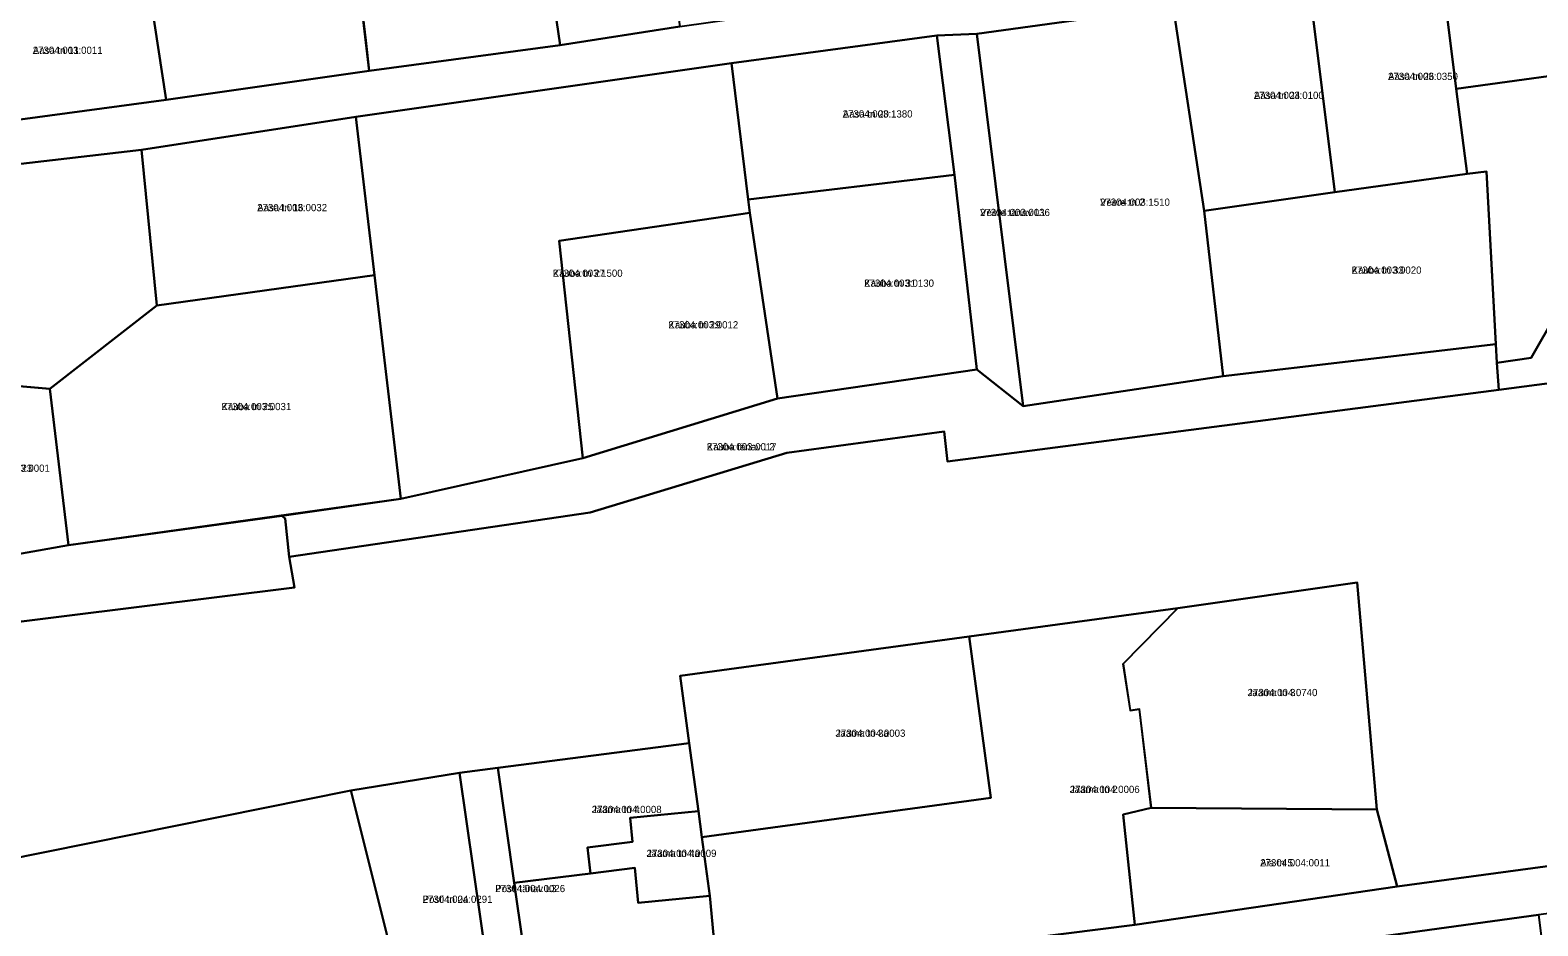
# Model space of a CAD drawing. Extents: x 603789 to 628102, y 6569852 to 6597259.
# Drawn here: x 622067.3 to 622380.3, y 6579689.4 to 6579875.4 of the extents above; entities that cross this region are included whole.
import ezdxf

# ---------------------------------------------------------------- set-up
doc = ezdxf.new("R2010")
doc.units = 0
for name, color, linetype in [('L_AADRESS', 7, 'Continuous'), ('PIIR', 7, 'Continuous'), ('TUNNUS', 7, 'Continuous')]:
    doc.layers.add(name, color=color, linetype=linetype)

msp = doc.modelspace()

# ---------------------------------------------------------------- linework, layer by layer
at = {"layer": 'PIIR'}
for points in [[(622170.72, 6579917.77), (622170.43, 6579919.31), (622194.97, 6579923.91), (622202.17, 6579876.21), (622177.32, 6579872.32)], [(622134.28, 6579895.91), (622132.4, 6579913.28), (622170.43, 6579919.31), (622170.72, 6579917.77), (622177.32, 6579872.32), (622137.73, 6579866.98)], [(622095.55, 6579860.95), (622091.61, 6579886.88), (622091.14, 6579889.62), (622113.84, 6579893.19), (622134.28, 6579895.91), (622136.98, 6579873.27), (622137.73, 6579866.98)], [(622360.27, 6579888.32), (622399.48, 6579895.23), (622401.63, 6579868.51), (622396.67, 6579867.81), (622363.4, 6579863.22)], [(622332.84, 6579884.63), (622360.27, 6579888.32), (622363.4, 6579863.22), (622365.62, 6579845.6), (622338.16, 6579841.8)], [(622091.61, 6579886.88), (622095.55, 6579860.95), (622044.62, 6579854.13), (622040.03, 6579879.14), (622067.85, 6579883.26)], [(622311.03, 6579837.93), (622304.61, 6579880.29), (622332.84, 6579884.63), (622338.16, 6579841.8)], [(622372.24, 6579800.71), (622371.83, 6579806.31), (622378.93, 6579807.36), (622399.14, 6579842.64), (622396.67, 6579867.81), (622401.63, 6579868.51), (622449.04, 6579874.75), (622522.3, 6579884.79), (622526.56, 6579866.38), (622539.24, 6579867.89), (622546.93, 6579836.13), (622548.52, 6579823.88)], [(622263.84, 6579874.66), (622304.61, 6579880.29), (622311.03, 6579837.93), (622315.01, 6579803.58), (622273.45, 6579797.29)], [(622212.9, 6579868.55), (622255.58, 6579874.31), (622259.25, 6579845.36), (622216.37, 6579840.25)], [(622255.58, 6579874.31), (622263.84, 6579874.66), (622273.45, 6579797.29), (622263.88, 6579804.9), (622259.25, 6579845.36)], [(622138.81, 6579824.51), (622134.92, 6579857.44), (622212.9, 6579868.55), (622216.37, 6579840.25), (622216.72, 6579837.46), (622177.17, 6579831.67), (622182.03, 6579786.5), (622144.3, 6579778.1)], [(622365.62, 6579845.6), (622363.4, 6579863.22), (622396.67, 6579867.81), (622399.14, 6579842.64), (622378.93, 6579807.36), (622371.83, 6579806.31), (622371.57, 6579810.23), (622369.66, 6579846.08)], [(622090.44, 6579850.56), (622134.92, 6579857.44), (622138.81, 6579824.51), (622093.61, 6579818.2)], [(621965.04, 6579811.57), (621962.83, 6579826.78), (621961.56, 6579835.58), (622090.44, 6579850.56), (622093.61, 6579818.2), (622071.41, 6579800.89), (622029.32, 6579804.59), (622028.08, 6579814.64), (622012.35, 6579813.75)], [(622222.48, 6579798.88), (622216.72, 6579837.46), (622216.37, 6579840.25), (622259.25, 6579845.36), (622263.88, 6579804.9)], [(622369.66, 6579846.08), (622371.57, 6579810.23), (622315.01, 6579803.58), (622311.03, 6579837.93), (622338.16, 6579841.8), (622365.62, 6579845.6)], [(622177.17, 6579831.67), (622216.72, 6579837.46), (622222.48, 6579798.88), (622182.03, 6579786.5)], [(622075.29, 6579768.47), (622071.41, 6579800.89), (622093.61, 6579818.2), (622138.81, 6579824.51), (622144.3, 6579778.1)], [(622119.58, 6579774.56), (622144.3, 6579778.1), (622182.03, 6579786.5), (622222.48, 6579798.88), (622263.88, 6579804.9), (622273.45, 6579797.29), (622315.01, 6579803.58), (622371.57, 6579810.23), (622371.83, 6579806.31), (622372.24, 6579800.71), (622257.76, 6579785.82), (622257.04, 6579792.02), (622224.39, 6579787.62), (622183.59, 6579775.25), (622121.09, 6579766.04), (622120.23, 6579773.96)], [(622071.41, 6579800.89), (622075.29, 6579768.47), (622044.4, 6579762.97), (622041.92, 6579764.98), (622038.53, 6579803.78)], [(622300.05, 6579713.85), (622297.61, 6579734.35), (622295.76, 6579734.07), (622294.24, 6579743.81), (622305.59, 6579755.32), (622342.78, 6579760.66), (622346.87, 6579713.5)], [(622305.59, 6579755.32), (622294.2, 6579743.81), (622295.71, 6579734.08), (622297.56, 6579734.35), (622300.05, 6579713.85), (622294.2, 6579712.49), (622296.66, 6579689.57), (622210.05, 6579678.6), (622208.44, 6579695.58), (622206.78, 6579707.81), (622266.78, 6579715.93), (622262.25, 6579749.45)], [(622206.78, 6579707.81), (622206.06, 6579713.17), (622204.15, 6579727.31), (622202.25, 6579741.32), (622262.25, 6579749.45), (622266.78, 6579715.93)], [(622164.38, 6579722.17), (622204.15, 6579727.31), (622206.06, 6579713.17), (622191.88, 6579711.82), (622192.36, 6579706.78), (622183.01, 6579705.61), (622183.68, 6579700.26), (622167.8, 6579698.28)], [(622156.45, 6579721.15), (622164.38, 6579722.17), (622167.8, 6579698.28), (622171.31, 6579673.7), (622163.73, 6579670.56)], [(622133.87, 6579717.48), (622156.45, 6579721.15), (622163.73, 6579670.56), (622146.33, 6579667.98), (622145.32, 6579671.81)], [(622133.87, 6579717.48), (622145.32, 6579671.81), (621710.27, 6579616.37), (621708.39, 6579631.66)], [(622191.88, 6579711.82), (622206.06, 6579713.17), (622206.78, 6579707.81), (622208.44, 6579695.58), (622193.56, 6579694.16), (622192.87, 6579701.41), (622183.68, 6579700.26), (622183.01, 6579705.61), (622192.36, 6579706.78)], [(622294.2, 6579712.49), (622300.05, 6579713.85), (622346.87, 6579713.5), (622351.14, 6579697.56), (622296.66, 6579689.57)], [(622167.8, 6579698.28), (622183.68, 6579700.26), (622192.87, 6579701.41), (622193.56, 6579694.16), (622208.44, 6579695.58), (622210.05, 6579678.6), (622171.31, 6579673.7)], [(622323.13, 6579683.73), (622380.48, 6579691.64), (622383.72, 6579665.81), (622353.92, 6579661.7), (622326.76, 6579657.96)]]:
    msp.add_lwpolyline(points, close=True, dxfattribs=at)
for points in [[(622044.62, 6579854.13), (622095.55, 6579860.95), (622137.73, 6579866.98), (622177.32, 6579872.32), (622202.17, 6579876.21), (622227.17, 6579879.74), (622252.37, 6579883.22), (622261.19, 6579884.01), (622295.06, 6579888.8), (622331.41, 6579893.82), (622352.89, 6579896.87), (622387.67, 6579901.78)], [(622399.48, 6579895.23), (622360.27, 6579888.32), (622332.84, 6579884.63), (622304.61, 6579880.29), (622263.84, 6579874.66), (622255.58, 6579874.31), (622212.9, 6579868.55), (622134.92, 6579857.44), (622090.44, 6579850.56), (621961.56, 6579835.58)], [(621409.97, 6579666.73), (621622.72, 6579719.42), (621662.81, 6579718.6), (621680.99, 6579702.57), (621686.54, 6579691.4), (621700.76, 6579693.54), (621721.11, 6579691.73), (621761.07, 6579693.39), (621848.7, 6579706.53), (621905.77, 6579719.38), (621951.29, 6579729.12), (621977.5, 6579736.71), (622008.7, 6579745.52), (622122.2, 6579759.63), (622121.09, 6579766.04), (622183.59, 6579775.25), (622224.39, 6579787.62), (622257.04, 6579792.02), (622257.76, 6579785.82), (622372.24, 6579800.71), (622548.52, 6579823.88), (622546.93, 6579836.13), (622636.07, 6579857.88)], [(622604.54, 6579779.17), (622546.88, 6579771.27), (622490.85, 6579763.08), (622450.48, 6579758.04), (622412.21, 6579753.29), (622417.7, 6579706.5), (622351.14, 6579697.56), (622346.87, 6579713.5), (622342.78, 6579760.66), (622305.59, 6579755.32), (622262.25, 6579749.45), (622202.25, 6579741.32), (622204.15, 6579727.31), (622164.38, 6579722.17), (622156.45, 6579721.15), (622133.87, 6579717.48), (621708.39, 6579631.66)], [(622044.4, 6579762.97), (622075.29, 6579768.47), (622119.58, 6579774.56), (622120.23, 6579773.96), (622121.09, 6579766.04), (622122.2, 6579759.63), (622008.7, 6579745.52)], [(622210.05, 6579678.6), (622296.66, 6579689.57), (622351.14, 6579697.56), (622417.7, 6579706.5), (622456.09, 6579711.79), (622497.48, 6579717.4), (622499.19, 6579705.61), (622444.84, 6579699.94), (622452.52, 6579635.19)], [(622444, 6579633.94), (622438.26, 6579691.55), (622428.59, 6579697.77), (622415.94, 6579696.33), (622380.48, 6579691.64), (622323.13, 6579683.73)]]:
    msp.add_lwpolyline(points, dxfattribs=at)

# ---------------------------------------------------------------- texts
at = {"layer": 'L_AADRESS'}
for s, p in [('Aasa tn 11', (622067.86, 6579870.5)), ('Aasa tn 26', (622349.23, 6579865.08)), ('Aasa tn 24', (622321.38, 6579861.14)), ('Aasa tn 20', (622236.01, 6579857.28)), ('Veere tn 2', (622289.43, 6579838.95)), ('Aasa tn 16', (622114.46, 6579837.82)), ('Veere tänav L1', (622264.52, 6579836.81)), ('Kauba tn 27', (622175.82, 6579824.19)), ('Kauba tn 33', (622341.67, 6579824.83)), ('Kauba tn 31', (622240.46, 6579822.12)), ('Kauba tn 29', (622199.82, 6579813.47)), ('Kauba tn 25', (622107.03, 6579796.49)), ('Kauba tänav L2', (622207.79, 6579788.13)), ('Kauba tn 23', (622056.91, 6579783.68)), ('Jaama tn 3', (622320.06, 6579737.08)), ('Jaama tn 3a', (622234.52, 6579728.63)), ('Jaama tn 2', (622283.16, 6579716.96)), ('Jaama tn 4', (622183.92, 6579712.79)), ('Jaama tn 4a', (622195.3, 6579703.67)), ('Aia tn 5', (622322.69, 6579701.71)), ('Posti tänav L3', (622163.88, 6579696.36)), ('Posti tn 2a', (622148.8, 6579694.13))]:
    msp.add_text(s, height=1.5, dxfattribs=at).set_placement(p)
at = {"layer": 'TUNNUS'}
for s, p in [('27304:003:0011', (622067.86, 6579870.5)), ('27304:003:0350', (622349.23, 6579865.08)), ('27304:003:0100', (622321.38, 6579861.14)), ('27304:003:1380', (622236.01, 6579857.28)), ('27304:003:1510', (622289.43, 6579838.95)), ('27304:003:0032', (622114.46, 6579837.82)), ('27304:003:0036', (622264.52, 6579836.81)), ('27304:003:1500', (622175.82, 6579824.19)), ('27304:003:0020', (622341.67, 6579824.83)), ('27304:003:0130', (622240.46, 6579822.12)), ('27304:003:0012', (622199.82, 6579813.47)), ('27304:003:0031', (622107.03, 6579796.49)), ('27304:003:0017', (622207.79, 6579788.13)), ('27304:003:0001', (622056.91, 6579783.68)), ('27304:004:0740', (622320.06, 6579737.08)), ('27304:004:0003', (622234.52, 6579728.63)), ('27304:004:0006', (622283.16, 6579716.96)), ('27304:004:0008', (622183.92, 6579712.79)), ('27304:004:0009', (622195.3, 6579703.67)), ('27304:004:0011', (622322.69, 6579701.71)), ('27304:004:0026', (622163.88, 6579696.36)), ('27304:004:0291', (622148.8, 6579694.13))]:
    msp.add_text(s, height=1.5, dxfattribs=at).set_placement(p)

doc.saveas('drawing.dxf')
